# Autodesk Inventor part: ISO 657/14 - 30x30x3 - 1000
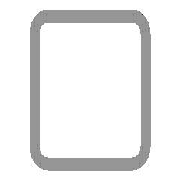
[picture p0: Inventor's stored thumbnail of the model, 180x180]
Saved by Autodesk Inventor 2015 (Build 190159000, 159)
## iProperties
Created: 2014-02
Part Number: ISO 657/14 - 30x30x3 - 1000
Material: Steel, Mild
Description: Hot-rolled steel sections - part 14: hot-finished structrual hollow sections - Dimensions and sectional properties
Document SubType Name: Modeling
Standard: ISO
Designer: 徐冠倫
Standard Revision: Third edition 2000-03-15
Standards Organization: ISO
Language: en-US
Size Designation: 30x30x3
Categories: <MemberInstance><Categories><Category DisplayName="Structural Shapes" InternalName="089c4875-fa83-4c05-b084-43b9cc11f5ed" Mnemonic="GRDR"><CategoryParameter Dis
Stock Number: 30x30x3
Density: 7.85 g/cm^3
Appearance: Semi-Polished
IsCustomPart: 1
G_L: 1000.000 mm
G_W: 30.000 mm
G_H: 30.000 mm
_CCFamilyMember: 8
_CCFamilyDisplayName: ISO 657/14 - 2000 (Square) - Hot-rolled steel sections - part 14: hot-finished structrual hollow sections - Dimensions and sectional properties
_FrameMemberDoc: Frame Member File
_Version: 15.0.0
_GetPNFromCC: 1
Author: 徐冠倫
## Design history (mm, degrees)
node "Start plane"
node "End plane"
sketch "Sketch"
  geometry: L1 (-15, -10.5)-(-15, 10.5); L2 (-10.5, 15)-(10.5, 15); L3 (15, 10.5)-(15, -10.5); L4 (10.5, -15)-(-10.5, -15); L5 (-10.5, 12)-(10.5, 12); L6 (12, 10.5)-(12, -10.5); L7 (10.5, -12)-(-10.5, -12); L8 (-12, -10.5)-(-12, 10.5); L9 (0, 22.305)-(0, -22.305) reference; L10 (-22.305, 0)-(22.305, 0) reference; A1 r 4.5 centre (-10.5, -10.5) between (-15, -10.5) and (-10.5, -15); A2 r 4.5 centre (-10.5, 10.5) between (-10.5, 15) and (-15, 10.5); A3 r 4.5 centre (10.5, 10.5) between (15, 10.5) and (10.5, 15); A4 r 4.5 centre (10.5, -10.5) between (10.5, -15) and (15, -10.5); A5 r 1.5 centre (-10.5, 10.5) between (-10.5, 12) and (-12, 10.5); A6 r 1.5 centre (10.5, 10.5) between (12, 10.5) and (10.5, 12); A7 r 1.5 centre (10.5, -10.5) between (10.5, -12) and (12, -10.5); A8 r 1.5 centre (-10.5, -10.5) between (-12, -10.5) and (-10.5, -12)
  constraints: 16 end point, 16 point on circle, 8 centre point, 8 tangent, 4 parallel, 3 equal radius, 2 perpendicular, 7 other
  dimensions: "d7" = 4.5 radius of A1 (= G_IR); "d10" = 30 distance between parallel lines of L2 L4 (= G_H); "d11" = 30 distance between parallel lines of L1 L3 (= G_W); "d12" = 3 distance between parallel lines of L3 L6 (= G_T); "d15" = 15 distance between parallel lines of L2 L10 (= 0.5 x d10); "d16" = 15 distance between parallel lines of L9 L3 (= 0.5 x d11)
extrude "Body" new body sketch "Sketch" stored distance "d3" = 1000 (= G_L); taper "d4" = 0 deg
node "Driven Length"
  sketch "Sketch3"
    geometry: L1 (0, 0)-(10, 0) reference
    constraints: 2 end point, 1 horizontal
  workplane "Work Plane3"
  sketch "Sketch4"
    geometry: L1 (-2, 0)-(12, 0) reference; L2 (-2, 1000)-(12, 1000) reference
    dimensions: "d18" = 1000 distance between parallel lines of L1 L2 (derived)
body "Solid1"
other parameters: "G_W" = 30 [user parameter; used in 1 equation term], "G_H" = 30 [user parameter; used in 1 equation term], "G_T" = 3 [user parameter; used in 1 equation term], "G_IR" = 4.5 [user parameter; used in 1 equation term], "G_L" = 1000 (= d18) [user parameter; used in 1 equation term], "G_OFFSET_START" = 0 [user parameter; used in 1 equation term], "G_OFFSET_END" = 0 [user parameter; used in 1 equation term], "d13" = 0 (computed from G_OFFSET_START), "d17" = 90 deg
